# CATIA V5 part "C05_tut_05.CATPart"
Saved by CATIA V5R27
Part number: Part1
Bounding box of the stored display mesh (mm): x -12 to 12, y 0 to 257, z -12 to 12
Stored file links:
  E:\_Deepak\2017_Deepak\CATIA\Resources\Tutorial Files\Tutorials\c05_catia_v5_6r2016_tut\C05_tut_05.CATPart
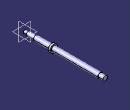
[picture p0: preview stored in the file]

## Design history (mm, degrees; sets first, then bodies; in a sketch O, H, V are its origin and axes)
Body1 (main body)
  Sketch1 on zx-plane, origin (0, 0, 0), H (-1, 0, 0), V (0, 0, 1)
    circle A1 centre (0, 0) radius 12
    circle A2 centre (0, 0) radius 8
    circle A3 centre (0, 0) radius 7
    circle A4 centre (0, 0) radius 6.5
    circle A5 centre (0, 0) radius 5
    radius A5 = 5
    radius A4 = 6.5
    radius A3 = 7
    radius A2 = 8
    radius A1 = 12
  MultiPad1: profile Sketch1, domains (length 257; length 257 / length -11; length 257 / length -35; length 241 / length -35; length 93 / length -87)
